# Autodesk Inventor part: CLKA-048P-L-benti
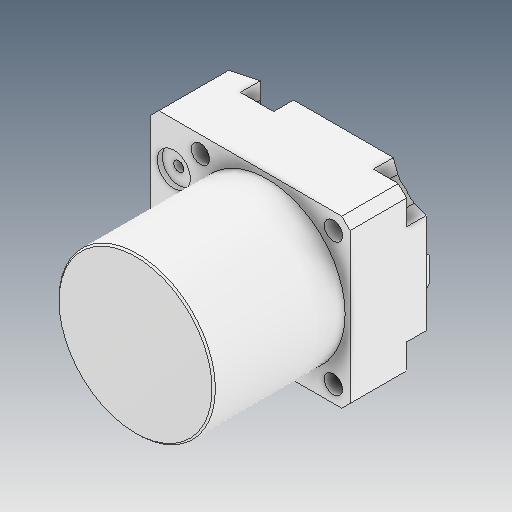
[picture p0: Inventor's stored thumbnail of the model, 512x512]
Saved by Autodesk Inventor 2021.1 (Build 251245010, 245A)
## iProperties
Created: 2021-06
Part Number: CLKA-048P-L-benti
Material: Ogólny
Document SubType Name: Modeling
Designer: user
Density: 1 g/cm^3
Appearance: Domyślna
Author: user
Revision Number: ÈÎºÎ
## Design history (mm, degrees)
feature "ÇÐ³ý-Ðý×ª6"
node "Bryła1"
